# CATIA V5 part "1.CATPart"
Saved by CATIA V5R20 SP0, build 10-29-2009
Part number: 1
Property "AB": 70 mm
Publications: "B", "Droite.1", "Droite.2", "Droite.3", "Plan.1", "A"
Bounding box of the stored display mesh (mm): x -50 to 50, y 0 to 67.147, z -19.779 to 0
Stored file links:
  D:\Dropbox\IAO_2012\IAO_2012_815_gcordenod\gcordenod\1.CATPart
  D:\Dropbox\IAO_2012\IAO_2012_815_gcordenod\gcordenod\Squelette_regulateur.CATProduct
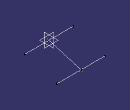
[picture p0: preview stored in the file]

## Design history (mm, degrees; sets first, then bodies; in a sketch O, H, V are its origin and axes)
External parameters (linked from other documents)
  External.AB = 70 mm
Body1 (main body)
  Point1 "B": type OnSurface, Support yz-plane, Length 70 {= External.AB}, Direction (0, 0.9592, -0.2826)
  Point2 "A": stored without definition
  Line1: type PtDir, RefPoint Point2, Direction yz-plane, Start -50, End 50
  Line2: type PtDir, RefPoint Point1, Direction yz-plane, Start -50, End 50
  Point3 "A": stored without definition
  Line3: type PtPt, FirstPoint Point3, SecondPoint Point1
  Plane1: type Offset, RefPlane yz-plane, Offset 0
  Point4 "A": stored without definition
  Point5 "A": (0, 0, 0), relative to Point4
